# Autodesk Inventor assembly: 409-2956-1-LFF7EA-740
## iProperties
Created: 2010-09
Part Number: 409-2956-1-LFF7EA-740
Document SubType Name: Weldment
Designer: S. Boerckel
Weld Material: Welded Steel Mild
Mass: 43145.5 g
Surface Area: 16478.2 cm^2
Volume: 5479.06 cm^3
Density: 7.87462 g/cm^3
Description: DISCHARGE SPOOL
Material: WELDMENT
SMR: =<MATERIAL>
Author: S. Boerckel
Revision Number: B
